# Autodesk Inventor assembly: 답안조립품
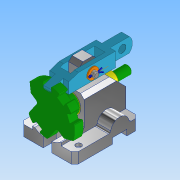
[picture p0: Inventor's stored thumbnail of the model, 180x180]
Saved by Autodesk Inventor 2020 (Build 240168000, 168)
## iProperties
Created: 2022-08
Part Number: 답안조립품
Document SubType Name: Assembly
Designer: user
Author: user
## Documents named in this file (8)
- C:\Users\user\Desktop\720806V1016\답안조립품.iam
- C:\Users\user\Desktop\720806V1016\본체.0004.ipt
- C:\Users\user\Desktop\720806V1016\부시.ipt
- C:\Users\user\Desktop\720806V1016\분할대.ipt
- C:\Users\user\Desktop\720806V1016\분할축.ipt
- C:\Users\user\Desktop\720806V1016\분할핀.ipt
- C:\Users\user\Desktop\720806V1016\와셔.ipt
- C:\Users\user\Desktop\720806V1016\클레비스핀.ipt
